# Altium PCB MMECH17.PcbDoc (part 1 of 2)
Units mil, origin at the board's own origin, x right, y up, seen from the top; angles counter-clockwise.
Board outline 2559.06 x 2205.16 mil, 4 copper layers (Top Layer, Ground Plane, Mid Layer 1, Bottom Layer), stack 56.756 mil thick; 96 components, 80 nets, 346 pads, 621 vias.
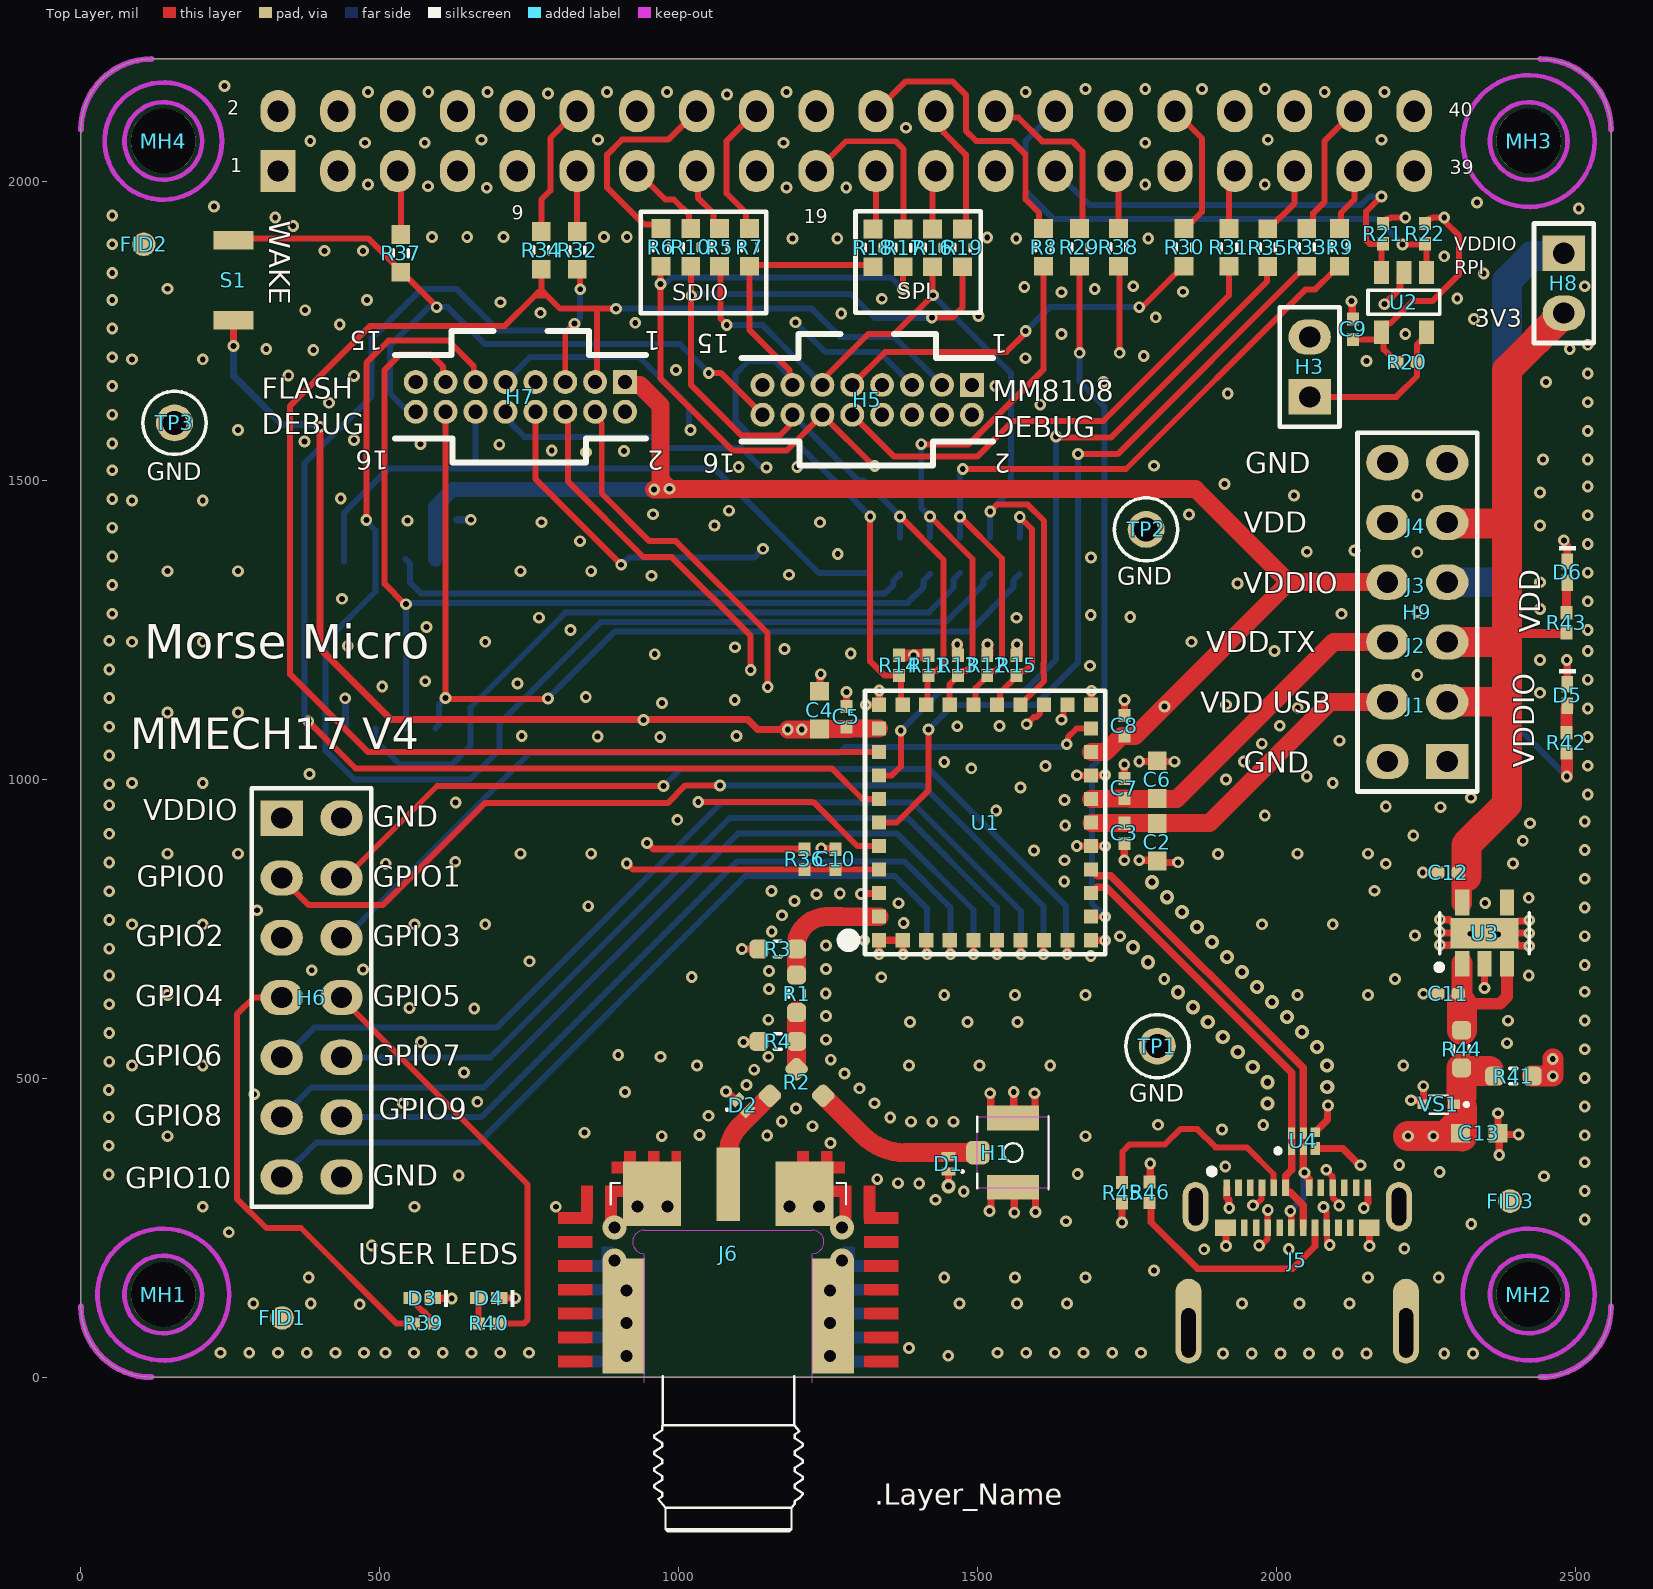
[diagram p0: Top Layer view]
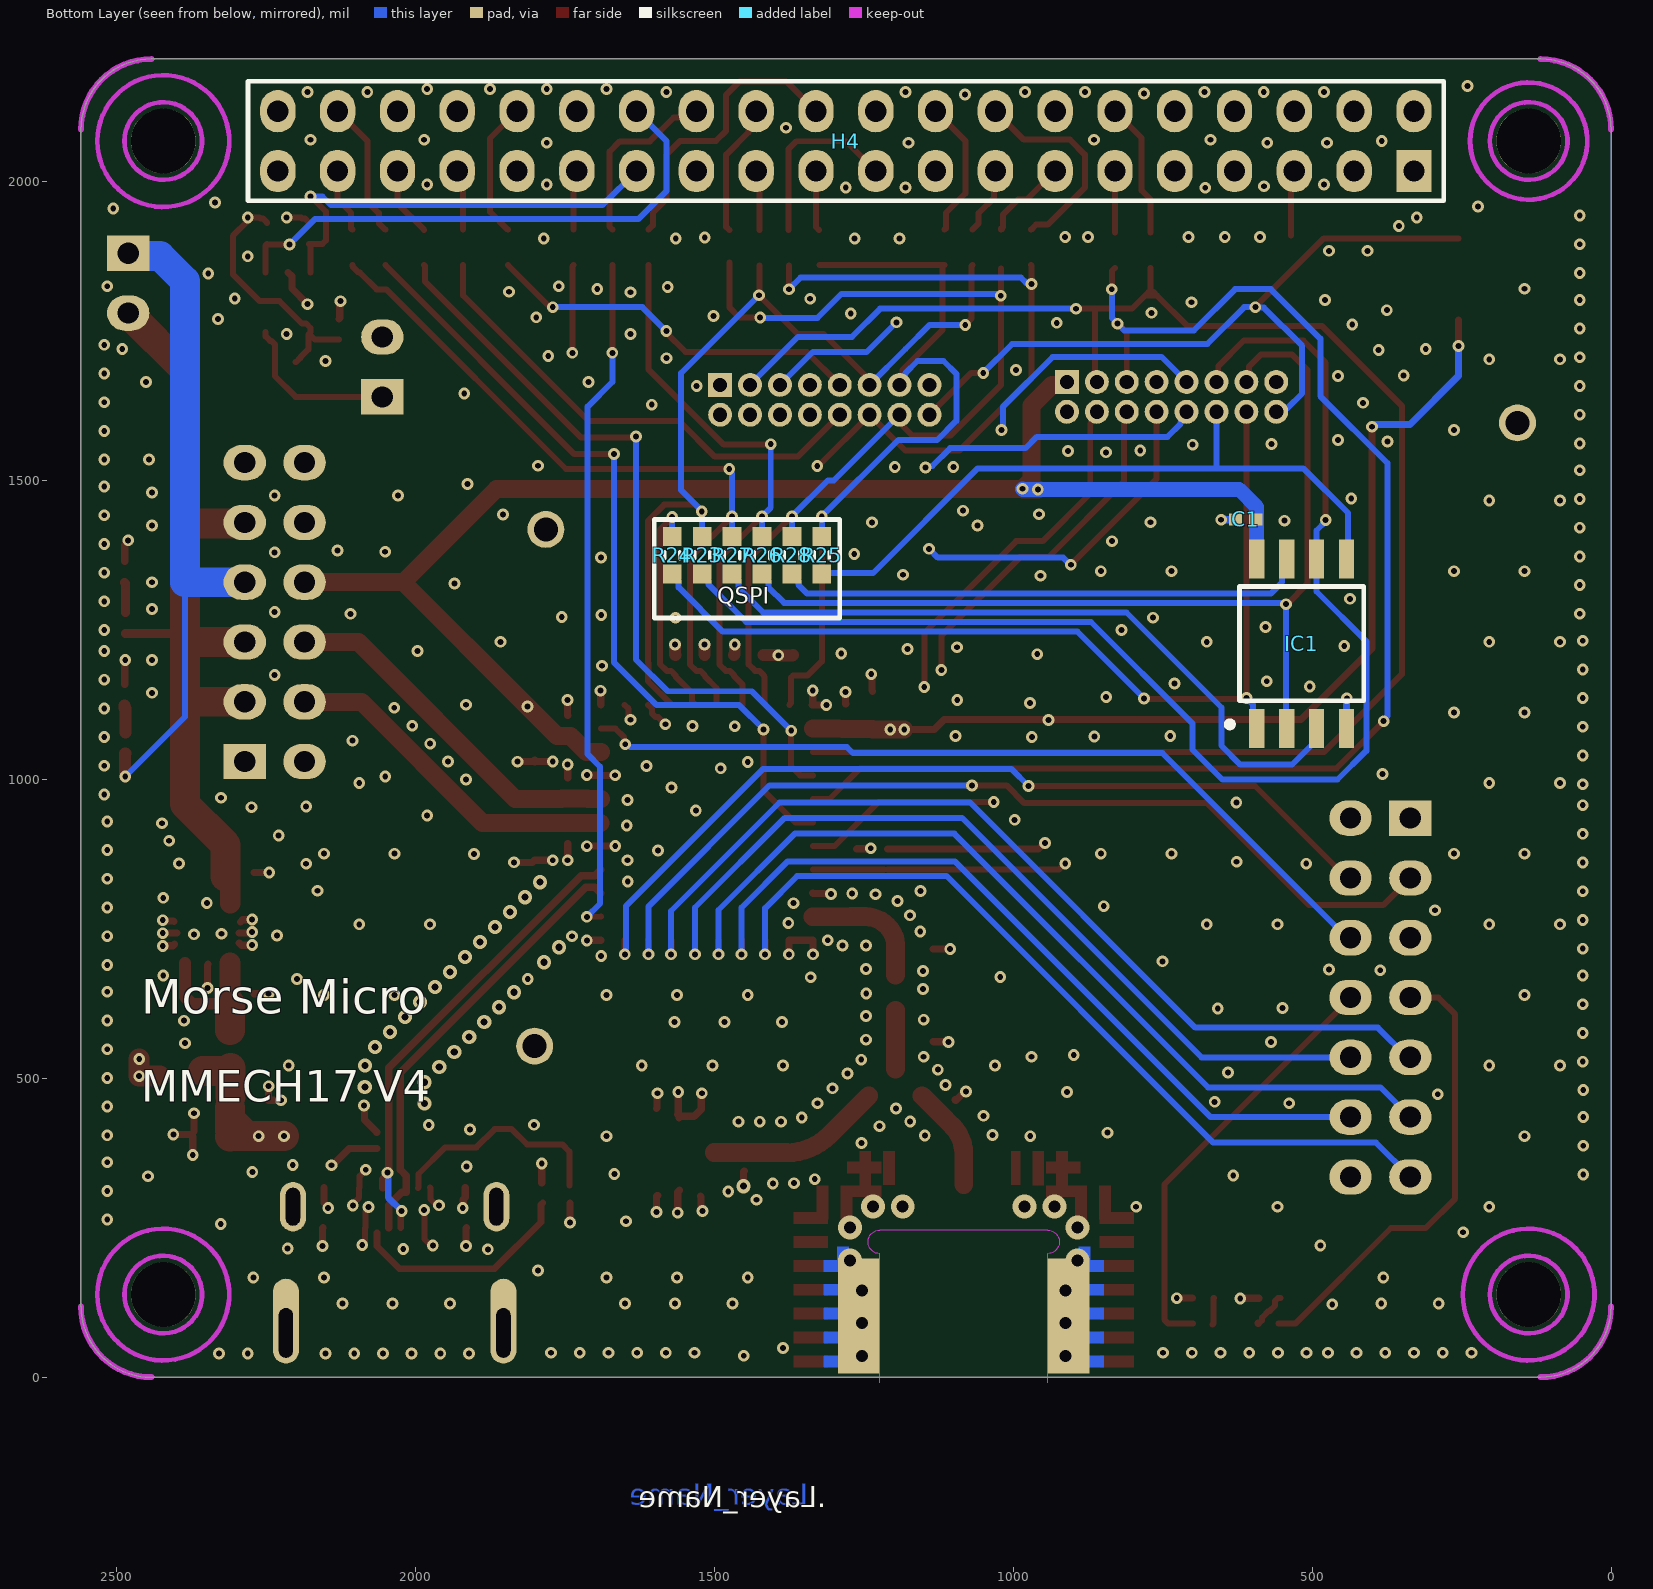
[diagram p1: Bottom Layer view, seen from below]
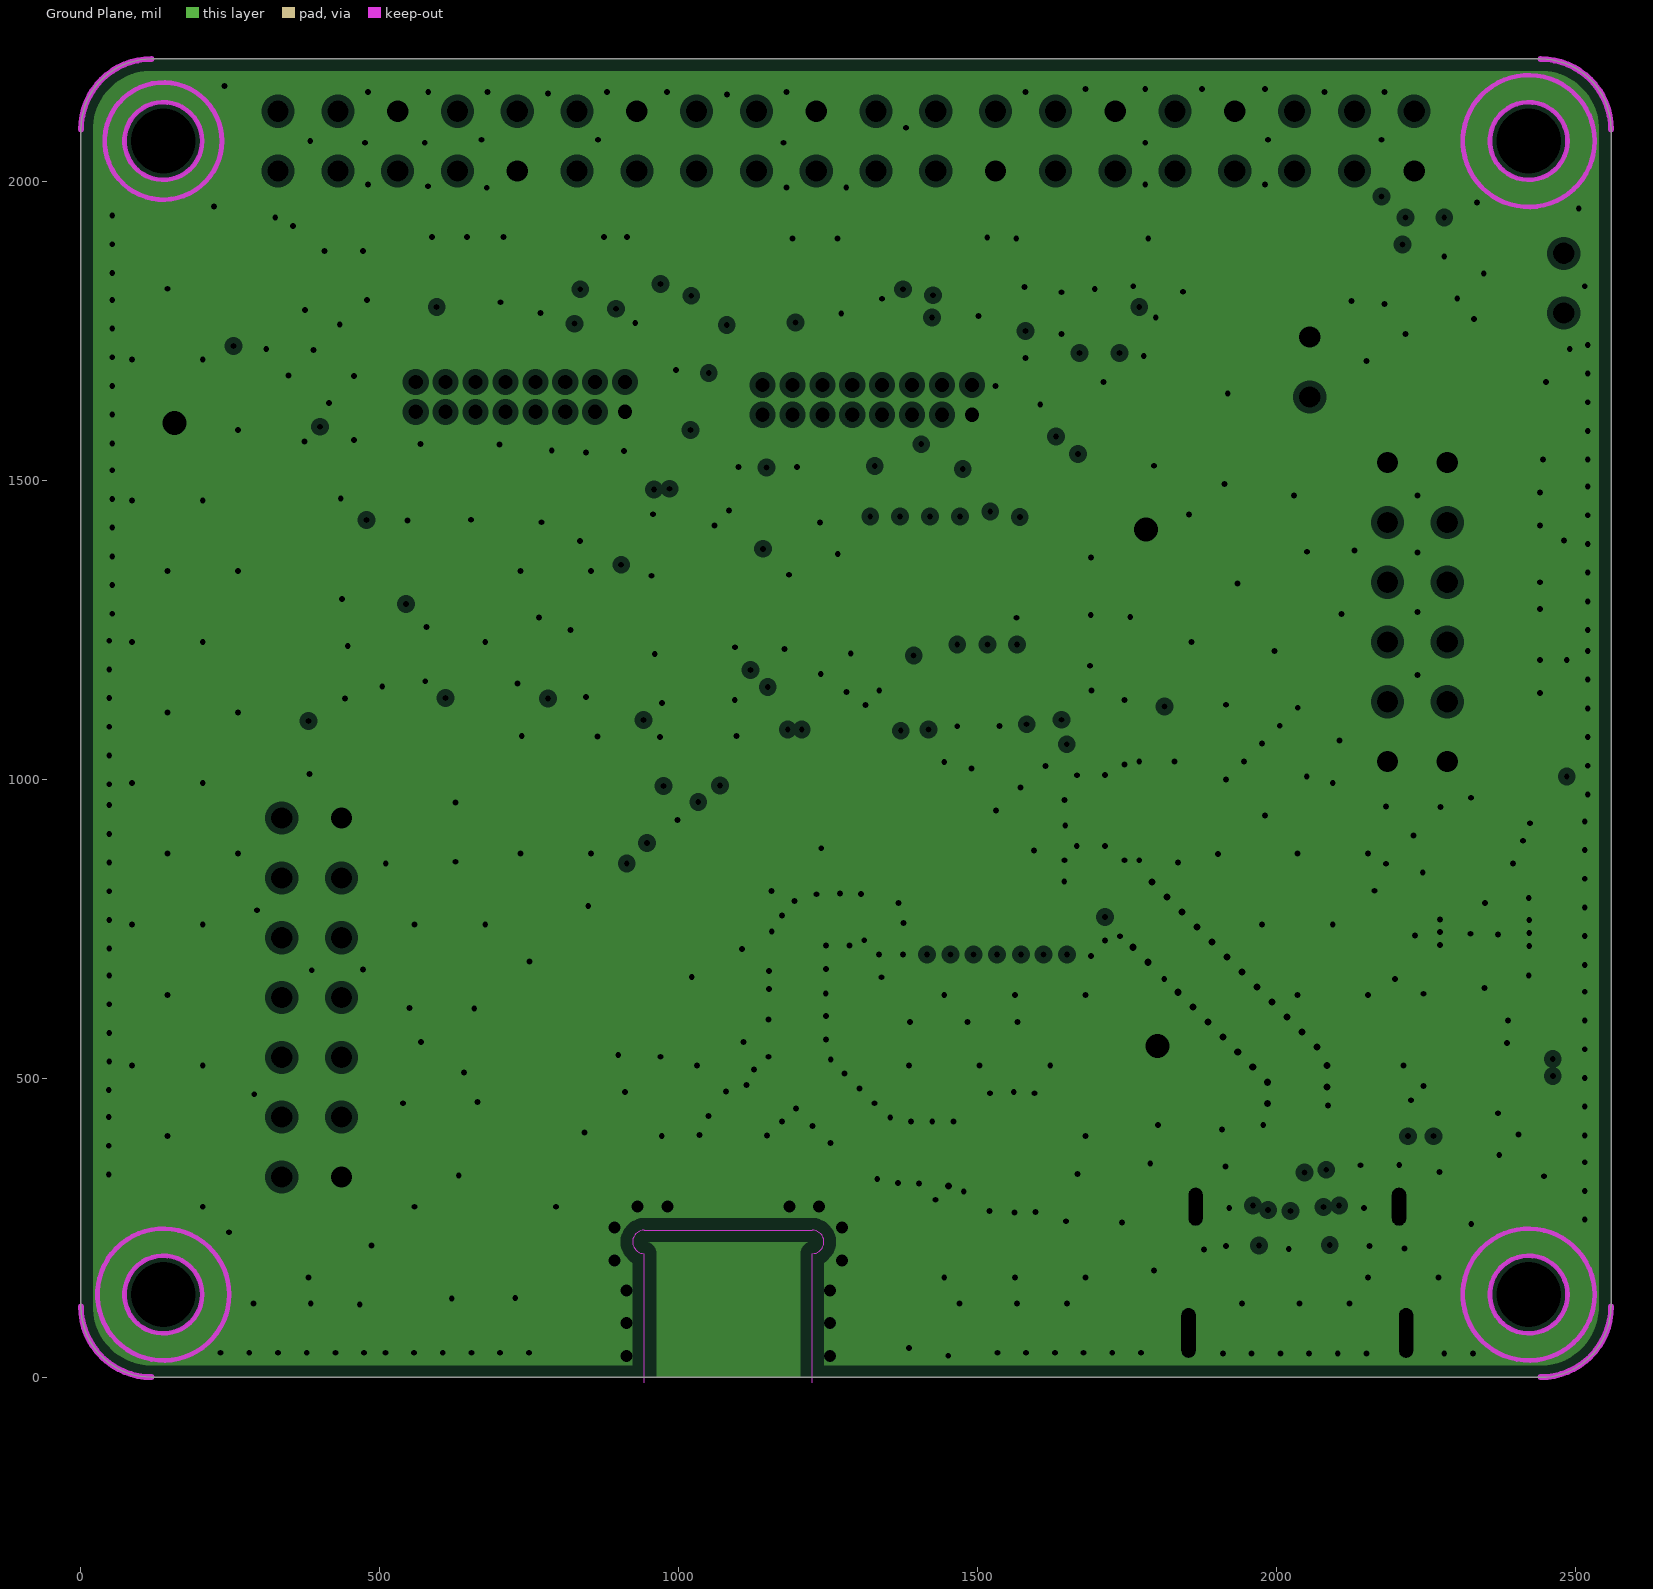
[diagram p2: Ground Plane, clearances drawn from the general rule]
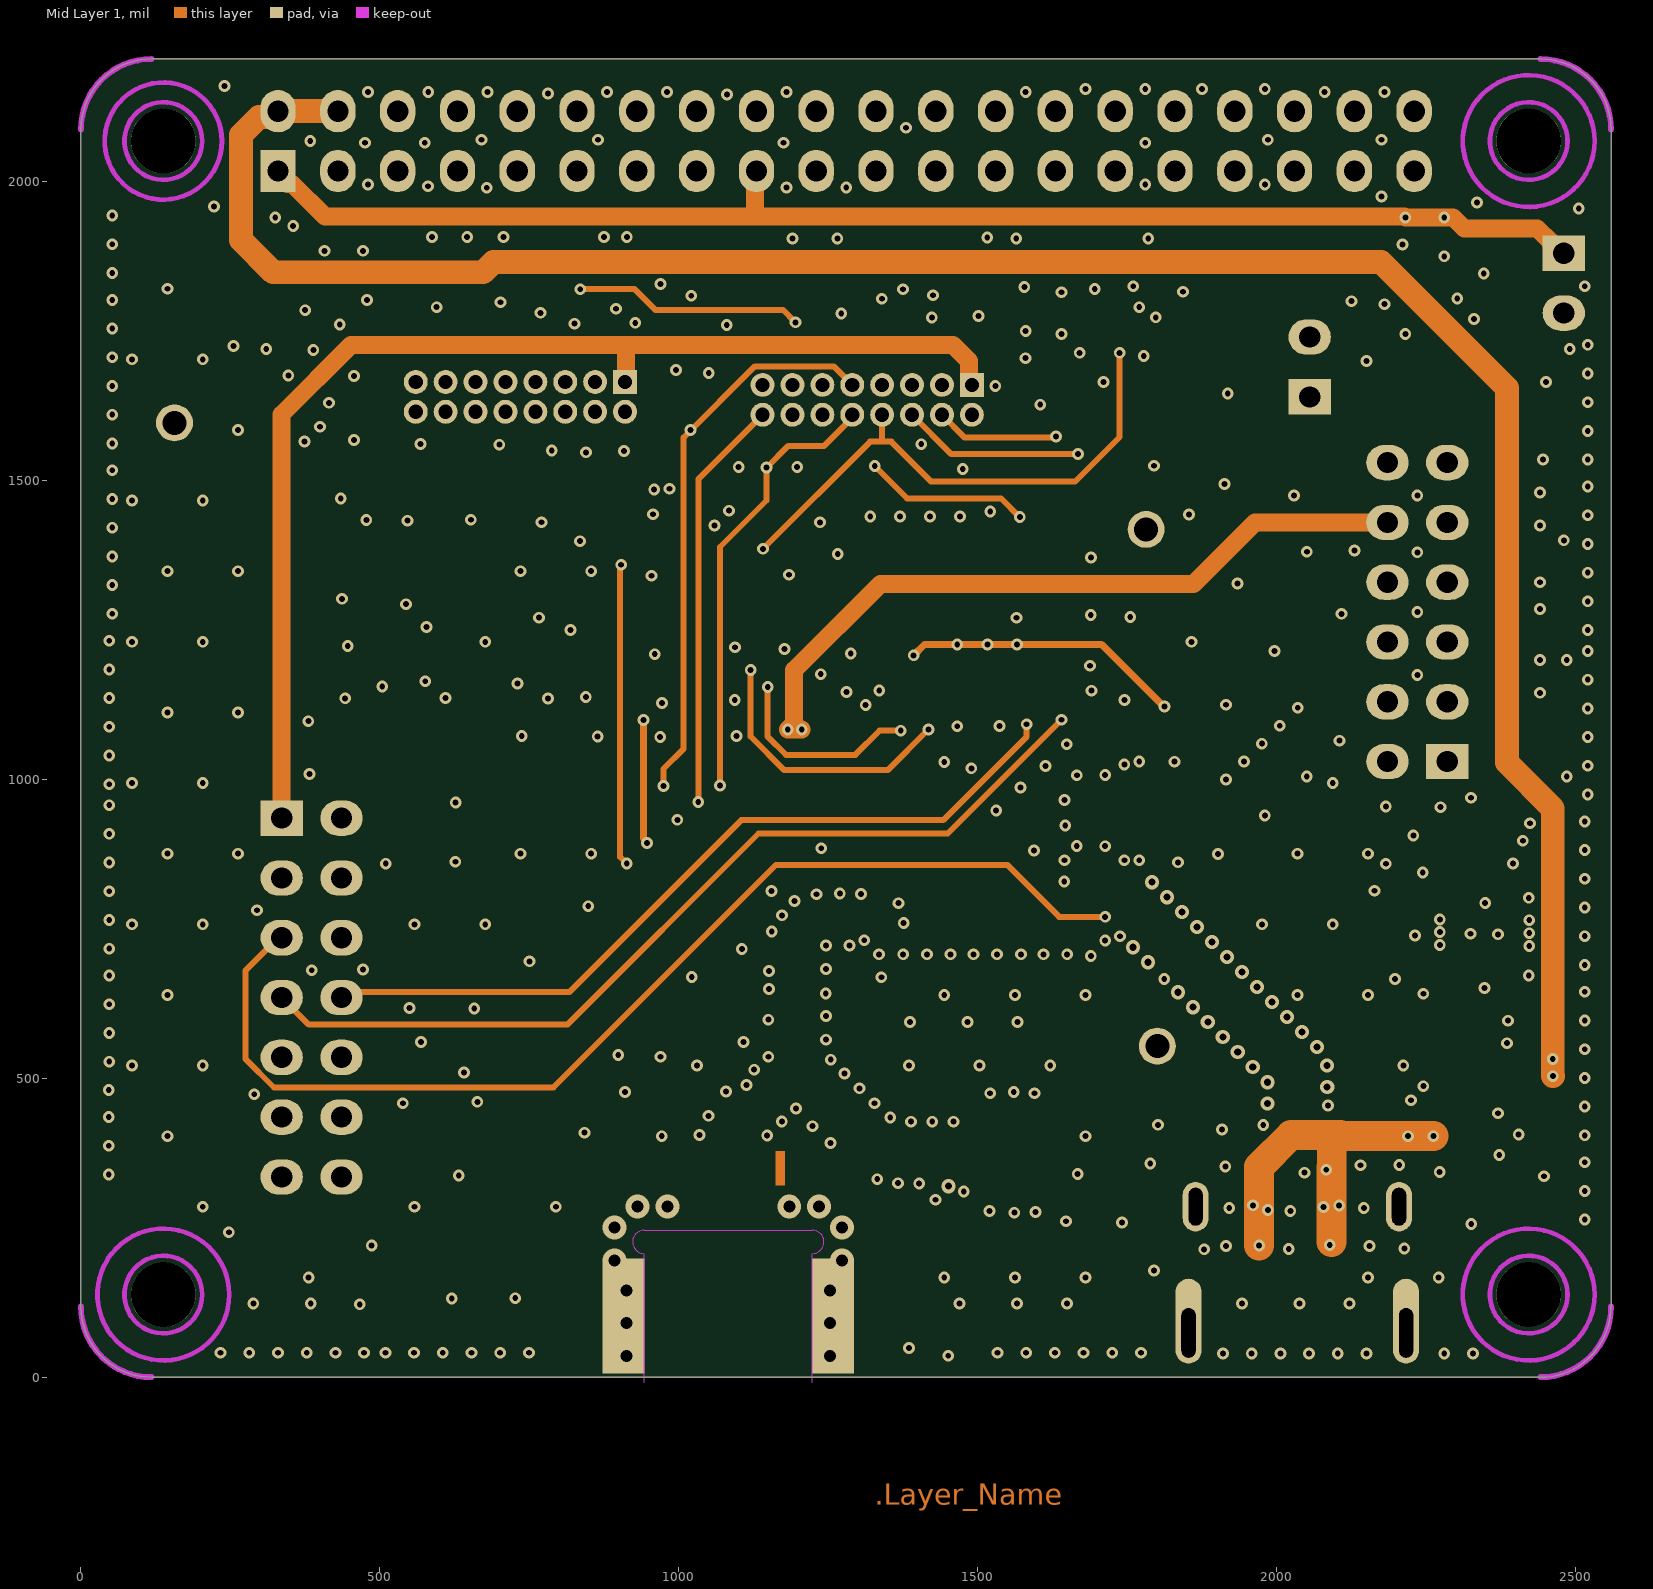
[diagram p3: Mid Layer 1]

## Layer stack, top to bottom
Top Solder: solder mask 0.787, PSR-4000-BN-Colour, Dk 4
Top Layer: signal copper 1.378
Dielectric 1: prepreg 12, PP, Dk 4.29
Ground Plane: plane copper 1.378, net GND
Dielectric 2: core 27.244, Core, Dk 4.29
Mid Layer 1: signal copper 1.378
Dielectric 3: prepreg 12, PP, Dk 4.29
Bottom Layer: signal copper 1.378
Bottom Solder: solder mask 0.787, PSR-4000-BN-Colour, Dk 4

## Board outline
0,118.54 0,2087.05 cw(c118.11,2087.05) 118.11,2205.16 2440.95,2205.16 cw(c2440.95,2087.05) 2559.06,2087.05 2559.06,118.54 2558.58,118.11 cw(c2440.47,118.11) 2440.47,0 118.54,0 118.11,0.43 cw(c118.11,118.54)

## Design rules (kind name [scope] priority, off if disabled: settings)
AcuteAngle [All] p0: scope1count=1 scope1_0_kind=Board scope1_0_value=Board scope2count=1 scope2_0_kind=Board scope2_0_value=Board commentlength=0 minimum=4.50000000000000E+0001
AcuteAngle [All] p1: minimum=4.50000000000000E+0001 checktracksonly=FALSE
AssemblyTestPointUsage [All] p0 off: scope1count=1 scope1_0_kind=Board scope1_0_value=Board scope2count=1 scope2_0_kind=Board scope2_0_value=Board commentlength=0
AssemblyTestPointUsage [All] p1 off:
AssemblyTestpoint [All] p0 off: scope1count=1 scope1_0_kind=Board scope1_0_value=Board scope2count=1 scope2_0_kind=Board scope2_0_value=Board commentlength=0
AssemblyTestpoint [All] p1 off: testpointundercomponent=TRUE minsize=40 maxsize=100 preferedsize=60 minholesize=0 maxholesize=40 preferedholesize=32 testpointgrid=1 usegrid=TRUE gridtolerance=0.01 allowsidetop=TRUE allowsidebottom=TRUE
BoardOutlineClearance [All] p0 off: scope1count=1 scope1_0_kind=Board scope1_0_value=Board scope2count=1 scope2_0_kind=Board scope2_0_value=Board commentlength=133 gap=5.98 // Protel DXP Scope 1 Expression Was: (not OnTopSilkscreen) AND (NOT OnBottomSilkscreen) and (not OnMultiLayer)    and  (not IsText)
BoardOutlineClearance BoardOutlineClearance_H2 [All] p0: scope1count=1 scope1_0_kind=Component scope1_0_value=H2 scope2count=1 scope2_0_kind=Board scope2_0_value=Board commentlength=0 gap=0
BoardOutlineClearance BoardOutlineClearance_H2 [InComponent('H2')] p1: gap=0 ignorepadtopadclearanceinfootprint=FALSE
BoardOutlineClearance [(not OnTopSilkscreen) AND (NOT OnBottomSilkscreen) and (not OnMultiLayer)    and  (not IsText)] p2: gap=5.98 ignorepadtopadclearanceinfootprint=FALSE
Clearance Clearance_SMA [All] p0 off: scope1count=1 scope1_0_kind=Footprint scope1_0_value=SM2924 scope2count=1 scope2_0_kind=Board scope2_0_value=Board commentlength=112 gap=0 // Protel DXP Scope 2 Expression Was: (OnLayer('Multi-Layer') OR OnLayer('Board') OR OnLayer('Keep-Out Layer'))
Clearance [All] p0: scope1count=1 scope1_0_kind=Board scope1_0_value=Board scope2count=1 scope2_0_kind=Board scope2_0_value=Board commentlength=0 gap=6
Clearance Clearance_RF [All] p0: scope1count=1 scope1_0_kind=NetClass scope1_0_value=RF-Net scope2count=1 scope2_0_kind=Board scope2_0_value=Board commentlength=0 gap=7.32
Clearance Clearance_RF_Poly [All] p0 off: scope1count=1 scope1_0_kind=Board scope1_0_value=Board scope2count=1 scope2_0_kind=NetClass scope2_0_value=RF-Net commentlength=50 gap=7.32 // Protel DXP Scope 1 Expression Was: (InPolygon)
Clearance Clearance_USB [All] p0 off: scope1count=1 scope1_0_kind=Board scope1_0_value=Board scope2count=1 scope2_0_kind=Board scope2_0_value=Board commentlength=66 gap=5.28 // Protel DXP Scope 1 Expression Was: InDifferentialPair('USB_D')
Clearance Clearance_SMA [HasFootprint('SM2924') vs (OnLayer('Multi-Layer') OR OnLayer('Board') OR OnLayer('Keep-Out Layer'))] p1: gap=0 ignorepadtopadclearanceinfootprint=TRUE
Clearance Clearance_USB [InDifferentialPair('USB_D')] p2: gap=5.28 ignorepadtopadclearanceinfootprint=TRUE except(6.2: Arc-Poly Track-Poly SMDPad-Poly)
Clearance Clearance_RF_Poly [(InPolygon) vs InNetClass('RF-Net')] p3: gap=7.32 ignorepadtopadclearanceinfootprint=TRUE
Clearance Clearance_RF [InNetClass('RF-Net')] p4: gap=7.32 ignorepadtopadclearanceinfootprint=TRUE
Clearance [All] p5: gap=6 ignorepadtopadclearanceinfootprint=TRUE
ComponentClearance ComponentClearance_Jumper [All] p0: scope1count=1 scope1_0_kind=Board scope1_0_value=Board scope2count=1 scope2_0_kind=Footprint scope2_0_value=FP-QPC02SXGN-RC-MFG commentlength=0 gap=0 collisioncheckmode=3
ComponentClearance [All] p0: scope1count=1 scope1_0_kind=Board scope1_0_value=Board scope2count=1 scope2_0_kind=Board scope2_0_value=Board commentlength=0 gap=10 collisioncheckmode=3
ComponentClearance ComponentClearance_Jumper [All vs HasFootprint('FP-QPC02SXGN-RC-MFG')] p1: gap=0 collisioncheckmode=3 verticalgap=-1 showdistances=FALSE
ComponentClearance [All] p2: gap=10 collisioncheckmode=3 verticalgap=10 showdistances=FALSE
DiffPairsRouting [All] p0 off: scope1count=1 scope1_0_kind=Board scope1_0_value=Board scope2count=1 scope2_0_kind=Board scope2_0_value=Board commentlength=66 // Protel DXP Scope 1 Expression Was: InDifferentialPair('USB_D')
DiffPairsRouting [InDifferentialPair('USB_D')] p1: maxlimit=7.1 minlimit=5.29 mostfreqgap=5.29 toplayer_mingap=6.5 toplayer_maxgap=6.5 toplayer_prefgap=6.5 toplayer_minwidth=12.5 toplayer_maxwidth=12.5 toplayer_prefwidth=12.5 bottomlayer_maxgap=5.29 bottomlayer_minwidth=11.02 bottomlayer_maxwidth=11.02 bottomlayer_prefwidth=11.02 impedanceprofiledriven=TRUE impedanceprofileid={D3D6B15B-8A59-4732-A24C-BA8DB3C77CBB} impedanceprofilevalue=90.000000 maxuncoupledlength=500
FabricationTestPointUsage [All] p0 off: scope1count=1 scope1_0_kind=Board scope1_0_value=Board scope2count=1 scope2_0_kind=Board scope2_0_value=Board commentlength=0 valid=0 allowmultiple=FALSE
FabricationTestPointUsage [All] p1 off: valid=0 allowmultiple=FALSE
FabricationTestpoint [All] p0 off: scope1count=1 scope1_0_kind=Board scope1_0_value=Board scope2count=1 scope2_0_kind=Board scope2_0_value=Board commentlength=0 side=3 testpointundercomponent=TRUE minsize=40 maxsize=100 preferedsize=60 minholesize=0 maxholesize=40 preferedholesize=32 testpointgrid=1
FabricationTestpoint [All] p1 off: side=3 testpointundercomponent=TRUE minsize=40 maxsize=100 preferedsize=60 minholesize=0 maxholesize=40 preferedholesize=32 testpointgrid=1 allowsidetop=TRUE allowsidebottom=TRUE usegrid=TRUE gridtolerance=0.01
FanoutControl Fanout_Default [All] p0 off: scope1count=1 scope1_0_kind=Board scope1_0_value=Board scope2count=1 scope2_0_kind=Board scope2_0_value=Board commentlength=30 // Fanout_Default (Default Rule)
FanoutControl Fanout_Small [All] p0 off: scope1count=1 scope1_0_kind=Board scope1_0_value=Board scope2count=1 scope2_0_kind=Board scope2_0_value=Board commentlength=84 // Protel DXP Scope 1 Expression Was: (CompPinCount < 5)   Fanout_Small (Default Rule)
FanoutControl Fanout_SOIC [All] p0 off: scope1count=1 scope1_0_kind=Board scope1_0_value=Board scope2count=1 scope2_0_kind=Board scope2_0_value=Board commentlength=71 // Protel DXP Scope 1 Expression Was: IsSOIC   Fanout_SOIC (Default Rule)
FanoutControl Fanout_LCC [All] p0 off: scope1count=1 scope1_0_kind=Board scope1_0_value=Board scope2count=1 scope2_0_kind=Board scope2_0_value=Board commentlength=69 // Protel DXP Scope 1 Expression Was: IsLCC   Fanout_LCC (Default Rule)
FanoutControl Fanout_BGA [All] p0 off: scope1count=1 scope1_0_kind=Board scope1_0_value=Board scope2count=1 scope2_0_kind=Board scope2_0_value=Board commentlength=69 // Protel DXP Scope 1 Expression Was: IsBGA   Fanout_BGA (Default Rule)
FanoutControl Fanout_BGA [IsBGA] p1 off: bgadir=Out bgaviamode=Centered fanoutstyle=Auto fanoutdirection=Alternating viagrid=1 // Fanout_BGA (Default Rule)
FanoutControl Fanout_LCC [IsLCC] p2 off: bgadir=Out bgaviamode=Centered fanoutstyle=Auto fanoutdirection=Alternating viagrid=1 // Fanout_LCC (Default Rule)
FanoutControl Fanout_SOIC [IsSOIC] p3 off: bgadir=Out bgaviamode=Centered fanoutstyle=Auto fanoutdirection=Alternating viagrid=1 // Fanout_SOIC (Default Rule)
FanoutControl Fanout_Small [(CompPinCount < 5)] p4 off: bgadir=Out bgaviamode=Centered fanoutstyle=Auto fanoutdirection=OutThenIn viagrid=1 // Fanout_Small (Default Rule)
FanoutControl Fanout_Default [All] p5 off: bgadir=Out bgaviamode=Centered fanoutstyle=Auto fanoutdirection=Alternating viagrid=1 // Fanout_Default (Default Rule)
Height [All] p0 off: scope1count=1 scope1_0_kind=Board scope1_0_value=Board scope2count=1 scope2_0_kind=Board scope2_0_value=Board commentlength=0
Height TP1 [All] p0: scope1count=1 scope1_0_kind=Component scope1_0_value=TP1 scope2count=1 scope2_0_kind=Board scope2_0_value=Board commentlength=0
Height TP1 [InComponent('TP1')] p1: minheight=0 maxheight=472.44 prefheight=118.11
Height [All] p2 off: minheight=0 maxheight=1000 prefheight=500
HoleSize [All] p0: scope1count=1 scope1_0_kind=Board scope1_0_value=Board scope2count=1 scope2_0_kind=Board scope2_0_value=Board commentlength=0 absolutevalues=TRUE maxlimit=200 minlimit=7.87 maxpercent=80.000 minpercent=20.000
HoleSize [All] p1: absolutevalues=TRUE maxlimit=200 minlimit=7.87 maxpercent=80.000 minpercent=20.000
HoleToHoleClearance [All] p0: scope1count=1 scope1_0_kind=Board scope1_0_value=Board scope2count=1 scope2_0_kind=Board scope2_0_value=Board commentlength=0
HoleToHoleClearance [All] p1: gap=8 allowstackedmicrovias=TRUE
LayerPairs [All] p0 off: scope1count=1 scope1_0_kind=Board scope1_0_value=Board scope2count=1 scope2_0_kind=Board scope2_0_value=Board commentlength=0 enforce=TRUE
LayerPairs [All] p1 off: enforce=TRUE
MatchedLengths MatchLengths_U1_Passives_J5 [All] p0: scope1count=1 scope1_0_kind=NetClass scope1_0_value=SDIO scope2count=1 scope2_0_kind=Board scope2_0_value=Board commentlength=0 tolerance=100 amplitude=200 gap=20 style=90-Degree
MatchedLengths MatchLengths_U1_Passives_J5 [InNetClass('SDIO')] p1: tolerance=100 checknetsindiffpair=FALSE checkdiffpairvsdiffpair=TRUE checkxsignals=TRUE checkothers=TRUE
MinimumSolderMaskSliver [All] p0 off: scope1count=1 scope1_0_kind=Board scope1_0_value=Board scope2count=1 scope2_0_kind=Board scope2_0_value=Board commentlength=108 // Protel DXP Scope 1 Expression Was: not InComponent('U4','U1','U5','U6','U7','U8','U9','U10', 'H7', 'H5')
MinimumSolderMaskSliver [not InComponent('U4','U1','U5','U6','U7','U8','U9','U10', 'H7', 'H5')] p1: minsoldermaskwidth=2.36
NetAntennae [All] p0: scope1count=1 scope1_0_kind=Board scope1_0_value=Board scope2count=1 scope2_0_kind=Board scope2_0_value=Board commentlength=0
PasteMaskExpansion [All] p0: scope1count=1 scope1_0_kind=Board scope1_0_value=Board scope2count=1 scope2_0_kind=Board scope2_0_value=Board commentlength=0 expansion=0
PlaneClearance [All] p0: scope1count=1 scope1_0_kind=Board scope1_0_value=Board scope2count=1 scope2_0_kind=Board scope2_0_value=Board commentlength=0 clearance=10
PlaneClearance [All] p1: clearance=10
PlaneConnect PlaneConnect_SMA [All] p0 off: scope1count=1 scope1_0_kind=Board scope1_0_value=Board scope2count=1 scope2_0_kind=Board scope2_0_value=Board commentlength=63 planeconnectstyle=Direct reliefexpansion=20 reliefentries=4 reliefconductorwidth=10 reliefairgap=10 // Protel DXP Scope 1 Expression Was: (HasFootprint('SM2924'))
PlaneConnect [All] p0: scope1count=1 scope1_0_kind=Board scope1_0_value=Board scope2count=1 scope2_0_kind=Board scope2_0_value=Board commentlength=0 planeconnectstyle=Relief reliefexpansion=20 reliefentries=4 reliefconductorwidth=10 reliefairgap=10
PlaneConnect PlaneConnect_SMA [(HasFootprint('SM2924'))] p1: planeconnectstyle=Direct reliefexpansion=20 reliefentries=4 reliefconductorwidth=10 reliefairgap=10
PlaneConnect [All] p2: pad.planeconnectstyle=Relief pad.reliefexpansion=20 pad.reliefentries=4 pad.reliefconductorwidth=10 pad.reliefairgap=10 via.planeconnectstyle=Direct via.reliefexpansion=20 via.reliefentries=4 via.reliefconductorwidth=10 via.reliefairgap=10
PolygonConnect PolygonConnect_SMA [All] p0 off: scope1count=1 scope1_0_kind=Board scope1_0_value=Board scope2count=1 scope2_0_kind=Board scope2_0_value=Board commentlength=63 connectstyle=Direct reliefconductorwidth=10 reliefentries=4 polygonreliefangle="90 Angle" // Protel DXP Scope 1 Expression Was: (HasFootprint('SM2924'))
PolygonConnect [All] p0: scope1count=1 scope1_0_kind=Board scope1_0_value=Board scope2count=1 scope2_0_kind=Board scope2_0_value=Board commentlength=0 connectstyle=Relief reliefconductorwidth=10 reliefentries=4 polygonreliefangle="90 Angle"
PolygonConnect PolygonConnect_SMA [(HasFootprint('SM2924'))] p1: connectstyle=Direct reliefconductorwidth=10 reliefentries=4 polygonreliefangle="90 Angle" airgapwidth=10
PolygonConnect [All] p2: thpad.connectstyle=Relief thpad.reliefconductorwidth=10 thpad.reliefentries=4 thpad.polygonreliefangle="90 Angle" thpad.airgapwidth=10 smdpad.connectstyle=Direct smdpad.reliefconductorwidth=10 smdpad.reliefentries=4 smdpad.polygonreliefangle="90 Angle" smdpad.airgapwidth=10 via.connectstyle=Direct via.reliefconductorwidth=10 via.reliefentries=4 via.polygonreliefangle="90 Angle" via.airgapwidth=10
RoutingCorners [All] p0: scope1count=1 scope1_0_kind=Board scope1_0_value=Board scope2count=1 scope2_0_kind=Board scope2_0_value=Board commentlength=0 cornerstyle=45-Degree minsetback=100 maxsetback=100
RoutingLayers [All] p0: scope1count=1 scope1_0_kind=Board scope1_0_value=Board scope2count=1 scope2_0_kind=Board scope2_0_value=Board commentlength=0 top layer=Automatic mid layer 3=Automatic bottom layer=Automatic
RoutingPriority [All] p0: scope1count=1 scope1_0_kind=Board scope1_0_value=Board scope2count=1 scope2_0_kind=Board scope2_0_value=Board commentlength=0
RoutingTopology [All] p0: scope1count=1 scope1_0_kind=Board scope1_0_value=Board scope2count=1 scope2_0_kind=Board scope2_0_value=Board commentlength=0 topology=Shortest
RoutingVias [All] p0: scope1count=1 scope1_0_kind=Board scope1_0_value=Board scope2count=1 scope2_0_kind=Board scope2_0_value=Board commentlength=0 holewidth=11.81 width=23.62 viastyle="Through Hole" minholewidth=7.87 minwidth=15.75 maxholewidth=28 maxwidth=50
RoutingVias [All] p1: holewidth=11.81 width=23.62 viastyle="Through Hole" minholewidth=7.87 minwidth=15.75 maxholewidth=28 maxwidth=50
ShortCircuit ShortCircuit_SMA [All] p0 off: scope1count=1 scope1_0_kind=Board scope1_0_value=Board scope2count=1 scope2_0_kind=Layer scope2_0_value=TOP commentlength=80 allowed=TRUE // Protel DXP Scope 1 Expression Was: (InNet('GND') AND HasFootprint('SM2924'))
ShortCircuit [All] p0: scope1count=1 scope1_0_kind=Board scope1_0_value=Board scope2count=1 scope2_0_kind=Board scope2_0_value=Board commentlength=0 allowed=FALSE
ShortCircuit ShortCircuit_SMA [(InNet('GND') AND HasFootprint('SM2924')) vs OnLayer('Multi-Layer')] p1: allowed=TRUE
ShortCircuit [All] p2: allowed=FALSE
SilkToBoardRegionClearance [All] p0: scope1count=1 scope1_0_kind=Board scope1_0_value=Board scope2count=1 scope2_0_kind=Board scope2_0_value=Board commentlength=0
SilkToSilkClearance [All] p0 off: scope1count=1 scope1_0_kind=Board scope1_0_value=Board scope2count=1 scope2_0_kind=Board scope2_0_value=Board commentlength=0
SilkToSilkClearance [All] p1 off: silktosilkclearance=8
SilkToSolderMaskClearance [All] p0 off: scope1count=1 scope1_0_kind=Board scope1_0_value=Board scope2count=1 scope2_0_kind=Board scope2_0_value=Board commentlength=44 // Protel DXP Scope 1 Expression Was: IsPad
SilkToSolderMaskClearance [IsPad] p1 off: minsilkscreentomaskgap=4 clearancetoexposedcopper=TRUE
SolderMaskExpansion [All] p0: scope1count=1 scope1_0_kind=Board scope1_0_value=Board scope2count=1 scope2_0_kind=Board scope2_0_value=Board commentlength=0 expansion=4
SolderMaskExpansion [All] p1: expansion=4 istentingtop=FALSE
SupplyNets "Schematic Supply Nets_11" [All] p0: scope1count=1 scope1_0_kind=Net scope1_0_value=VDD_TX scope2count=1 scope2_0_kind=Board scope2_0_value=Board commentlength=0 voltage=0.000
SupplyNets "Schematic Supply Nets_10" [All] p0: scope1count=1 scope1_0_kind=Net scope1_0_value=VDD scope2count=1 scope2_0_kind=Board scope2_0_value=Board commentlength=0 voltage=0.000
SupplyNets "Schematic Supply Nets_8" [All] p0: scope1count=1 scope1_0_kind=Net scope1_0_value=VDD_3V3 scope2count=1 scope2_0_kind=Board scope2_0_value=Board commentlength=0 voltage=0.000
SupplyNets "Schematic Supply Nets_6" [All] p0: scope1count=1 scope1_0_kind=Net scope1_0_value=VDDIO_RPI scope2count=1 scope2_0_kind=Board scope2_0_value=Board commentlength=0 voltage=0.000
SupplyNets "Schematic Supply Nets_5" [All] p0: scope1count=1 scope1_0_kind=Net scope1_0_value=VDD5 scope2count=1 scope2_0_kind=Board scope2_0_value=Board commentlength=0 voltage=0.000
SupplyNets "Schematic Supply Nets_4" [All] p0: scope1count=1 scope1_0_kind=Net scope1_0_value=5V_USB scope2count=1 scope2_0_kind=Board scope2_0_value=Board commentlength=0 voltage=0.000
SupplyNets "Schematic Supply Nets_3" [All] p0: scope1count=1 scope1_0_kind=Net scope1_0_value=GND scope2count=1 scope2_0_kind=Board scope2_0_value=Board commentlength=0 voltage=0.000
SupplyNets "Schematic Supply Nets_2" [All] p0: scope1count=1 scope1_0_kind=Net scope1_0_value=VDD_USB scope2count=1 scope2_0_kind=Board scope2_0_value=Board commentlength=0 voltage=0.000
SupplyNets "Schematic Supply Nets_1" [All] p0: scope1count=1 scope1_0_kind=Net scope1_0_value=VDD5_RPI scope2count=1 scope2_0_kind=Board scope2_0_value=Board commentlength=0 voltage=0.000
SupplyNets "Schematic Supply Nets" [All] p0: scope1count=1 scope1_0_kind=Net scope1_0_value=VDDIO scope2count=1 scope2_0_kind=Board scope2_0_value=Board commentlength=0 voltage=0.000
SupplyNets "Schematic Supply Nets_11" [InNet('VDD_TX')] p1: voltage=0.000
SupplyNets "Schematic Supply Nets_10" [InNet('VDD')] p2: voltage=0.000
SupplyNets "Schematic Supply Nets_8" [InNet('VDD_3V3')] p3: voltage=0.000
SupplyNets "Schematic Supply Nets_6" [InNet('VDDIO_RPI')] p4: voltage=0.000
SupplyNets "Schematic Supply Nets_5" [InNet('VDD5')] p5: voltage=0.000
SupplyNets "Schematic Supply Nets_4" [InNet('5V_USB')] p6: voltage=0.000
SupplyNets "Schematic Supply Nets_3" [InNet('GND')] p7: voltage=0.000
SupplyNets "Schematic Supply Nets_2" [InNet('VDD_USB')] p8: voltage=0.000
SupplyNets "Schematic Supply Nets_1" [InNet('VDD5_RPI')] p9: voltage=0.000
SupplyNets "Schematic Supply Nets" [InNet('VDDIO')] p10: voltage=0.000
UnConnectedPin [All] p0 off: scope1count=1 scope1_0_kind=Board scope1_0_value=Board scope2count=1 scope2_0_kind=Board scope2_0_value=Board commentlength=0
UnConnectedPin [All] p1 off:
UnRoutedNet [All] p0: scope1count=1 scope1_0_kind=Board scope1_0_value=Board scope2count=1 scope2_0_kind=Board scope2_0_value=Board commentlength=0
UnRoutedNet [All] p1: checkbadconnections=TRUE
UnpouredPolygon [All] p0: scope1count=1 scope1_0_kind=Board scope1_0_value=Board scope2count=1 scope2_0_kind=Board scope2_0_value=Board commentlength=0
Width [All] p0: scope1count=1 scope1_0_kind=Board scope1_0_value=Board scope2count=1 scope2_0_kind=Board scope2_0_value=Board commentlength=0 maxlimit=50 minlimit=10 preferedwidth=10
Width "RF Width" [All] p0: scope1count=1 scope1_0_kind=NetClass scope1_0_value=RF-Net scope2count=1 scope2_0_kind=Board scope2_0_value=Board commentlength=0 maxlimit=35.43 minlimit=7 preferedwidth=10
Width "RF Width" [InNetClass('RF-Net')] p1: maxlimit=35.43 minlimit=7 preferedwidth=10 toplayer_minwidth=31.5 toplayer_maxwidth=31.5 toplayer_prefwidth=31.5 impedanceprofiledriven=TRUE impedanceprofileid={2BAD1660-FF1E-4629-AB45-93BC2CD73358} impedanceprofilevalue=50.000000 minimp=50.000000 maximp=50.000000 favimp=50.000000
Width [All] p2: maxlimit=50 minlimit=10 preferedwidth=10 minimp=50.000000 maximp=50.000000 favimp=50.000000
8 further rules are at their usual default settings.

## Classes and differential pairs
component class SOT-23: U3
net class RF-Net: NetD1_2 NetD2_2 NetR1_1 NetR1_2
component class PCB_PATTERN: FID1 FID2 FID3 MH1 MH2 MH3 MH4
component class COMP_OTHER: H1 H3 H4 H6 H8 H9 J5 S1 U1 U2 U4
component class CHIP_OTHER: C2 C4 C6 C13 D3 D4 D5 D6 R1 R3 R4 R37 R41 R44
component class CHIP_MICRO: C1 C3 C5 C7 C8 C9 C10 C11 C12 R2 R5 R6 R7 R8 R9 R10 R11 R12 R13 R14 R15 R16 R17 R18 R19 R20 R21 R22 R23 R24 R25 R26 R27 R28 R29 R30 R31 R32 R33 R34 R35 R36 R38 R39 R40 R42 R43 R45 R46 VS1
component class MMECH17_Power: C11 C12 C13 D5 D6 FID1 FID2 FID3 H8 H9 J1 J2 J3 J4 J5 MH1 MH2 MH3 MH4 R41 R42 R43 R44 R45 R46 TP1 TP2 TP3 U3 U4 VS1
component class MMECH17_Module: C1 C2 C3 C4 C5 C6 C7 C8 C9 C10 D1 D2 D3 D4 H1 H3 H4 H5 H6 H7 IC1 J6 R1 R2 R3 R4 R5 R6 R7 R8 R9 R10 R11 R12 R13 R14 R15 R16 R17 R18 R19 R20 R21 R22 R23 R24 R25 R26 R27 R28 R29 R30 R31 R32 R33 R34 R35 R36 R37 R38 R39 R40 S1 U1 U2
differential pair " ": +USB_D_P -USB_D_N

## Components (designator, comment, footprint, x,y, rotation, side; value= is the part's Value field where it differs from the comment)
C1 "C0402C104K8RACTU" 0402_cap 611.22,1435.04 r180 bottom
C2 "GRM188R61E106MA73J" 0603_cap 1800,895 r270 top
C3 "C0402C104K8RACTU" 0402_cap 1745,910 r270 top
C4 "GRM188R61E106MA73J" 0603_cap 1235.24,1116.14 r90 top
C5 "C0402C104K8RACTU" 0402_cap 1280.16,1105 r270 top
C6 "GRM188R61E106MA73J" 0603_cap 1800,1000 r90 top
C7 "C0402C104K8RACTU" 0402_cap 1745,985 r90 top
C8 "C0402C104K8RACTU" 0402_cap 1745,1090 r90 top
C9 "C0402C104K8RACTU" 0402_cap 2127.5,1753.08 r270 top
C10 "JMK105BJ225MV-F" 0402_cap 1261.72,866.34 r90 top
C11 "CL05A106MP8NUB8" 0402_cap_rnd 2286.42,641.73 r180 top
C12 "CL05A106MP8NUB8" 0402_cap_rnd 2286.42,844.49 r180 top
C13 "GRM188R61E106MA73J" 0603_cap 2338.58,408.46 r0 top
D1 "ESD103B102ELE6327XTMA1" INF-TSLP-2-20_V 1450.79,357.28 r180 top
D2 "ESD103B102ELE6327XTMA1" INF-TSLP-2-20_V 1106.49,455.52 r45 top
D3 "XZVGR68W-3" LED_0402_GREEN 570.87,132.87 r0 top
D4 "XZMDK68W-2" LED_0402_RED 682.09,132.87 r0 top
D5 "XZVGR68W-3" LED_0402_GREEN 2485.8,1141.26 r90 top
D6 "XZVGR68W-3" LED_0402_GREEN 2485.8,1346.93 r90 top
FID1 "1mm Round Fiducial, 0.5mm Space" FIDUCIAL_1MM 336.36,99.56 r90 top
FID2 "1mm Round Fiducial, 0.5mm Space" FIDUCIAL_1MM 105,1895 r0 top
FID3 "1mm Round Fiducial, 0.5mm Space" FIDUCIAL_1MM 2390,295 r90 top
H1 "U.FL-R-SMT" U_FL-R-SMT 1559.06,375.98 r270 top
H3 "DNF" HDR1X2_DNF 2055,1690 r90 top
H4 "PPPC202LFBN-RC" HDR2X20F 1279.72,2067.72 r0 bottom
H5 "FTSH-108-01-F-D-K" FTSH_108_D_K 1315,1635 r180 top
H6 "PBC07DFAN" HDR2X7 385.8,635.41 r270 top
H7 "FTSH-108-01-F-D-K" FTSH_108_D_K 735,1640 r180 top
H8 "2011-1X02G00SB-1" HDR1X2 2480,1830 r270 top
H9 "90131-0126" HDR2X6 2235,1280 r90 top
IC1 "W25Q64JVSSIQ" SOIC127P790X216-8N 517.65,1227.35 r90 bottom
J1 "QPC02SXGN-RC" FP-QPC02SXGN-RC-MFG 2232.28,1124.02 r0 top
J2 "QPC02SXGN-RC" FP-QPC02SXGN-RC-MFG 2232.28,1223.43 r0 top
J3 "QPC02SXGN-RC" FP-QPC02SXGN-RC-MFG 2232.28,1323.82 r0 top
J4 "QPC02SXGN-RC" FP-QPC02SXGN-RC-MFG 2232.28,1423.23 r0 top
J5 "2012670005" USB-C_RCP 2034.29,196.02 r0 top locked
J6 "SM2924" SM2924 1082.68,35.83 r90 top
MH1 "PAD0009" MH_300_275_NPTH 137.8,138.66 r0 top
MH2 "PAD0009" MH_300_275_NPTH 2421.26,138.66 r0 top
MH3 "PAD0009" MH_300_275_NPTH 2421.26,2067.8 r0 top
MH4 "PAD0009" MH_300_275_NPTH 137.8,2067.8 r0 top
R1 "RC0603JR-070RL" 0603_res_rnd 1196.85,641.73 r270 top
R2 "RC0603JR-070RL" 0603_res_ab_ra 1174.58,493.48 r225 top
R3 "RC0603JR-070RL" 0603_res_rnd 1165.35,716.54 r0 top
R4 "RC0603JR-070RL" 0603_res_rnd 1165.35,562.01 r0 top
R5 "ERJ-3GEY0R00V" 0603_res 1068.17,1890 r90 top
R6 "ERJ-3GEY0R00V" 0603_res 970,1890 r90 top
R7 "ERJ-3GEY0R00V" 0603_res 1117.9,1889.87 r90 top
R8 "ERJ-3GEY0R00V" 0603_res 1610,1890 r90 top
R9 "ERJ-3GEY0R00V" 0603_res 2105,1890 r90 top
R10 "ERJ-3GEY0R00V" 0603_res 1020,1890 r90 top
R11 "MCR01MZPF4702" 0402_res 1417.32,1190.94 r270 top
R12 "MCR01MZPF4702" 0402_res 1515.75,1190.94 r270 top
R13 "MCR01MZPF4702" 0402_res 1466.54,1190.94 r270 top
R14 "MCR01MZPF4702" 0402_res 1368.11,1190.94 r270 top
R15 "MCR01MZPF4702" 0402_res 1564.96,1190.94 r270 top
R16 "ERJ-3GEY0R00V" 0603_res 1424.43,1889.17 r90 top
R17 "ERJ-3GEY0R00V" 0603_res 1375.34,1889.17 r90 top
R18 "ERJ-3GEY0R00V" 0603_res 1324.43,1889.17 r90 top
R19 "ERJ-3GEY0R00V" 0603_res 1474.43,1889.17 r90 top
R20 "RC0402FR-073K9L" 0402_res 2217.5,1698.08 r0 top
R21 "RC0402FR-073K9L" 0402_res 2177.5,1913.08 r270 top
R22 "RC0402FR-073K9L" 0402_res 2247.5,1913.08 r270 top
R23 "ERJ-3GEY0R00V" 0603_res 1520,1375 r270 bottom
R24 "ERJ-3GEY0R00V" 0603_res 1570,1375 r270 bottom
R25 "ERJ-3GEY0R00V" 0603_res 1320,1375 r270 bottom
R26 "ERJ-3GEY0R00V" 0603_res 1420,1375 r270 bottom
R27 "ERJ-3GEY0R00V" 0603_res 1470,1375 r270 bottom
R28 "ERJ-3GEY0R00V" 0603_res 1370,1375 r270 bottom
R29 "ERJ-3GEY0R00V" 0603_res 1670,1890 r90 top
R30 "ERJ-3GEY0R00V" 0603_res 1845,1890 r90 top
R31 "ERJ-3GEY0R00V" 0603_res 1920,1890 r90 top
R32 "ERJ-3GEY0R00V" 0603_res 830,1885 r90 top
R33 "ERJ-3GEY0R00V" 0603_res 2050,1890 r90 top
R34 "ERJ-3GEY0R00V" 0603_res 770,1885 r90 top
R35 "ERJ-3GEY0R00V" 0603_res 1984.96,1889.7 r90 top
R36 "RC0402FR-07220KL" 0402_res 1210.06,866.34 r270 top
R37 "RG1608P-103-B-T5" 0603_res 535,1880 r90 top
R38 "ERJ-3GEY0R00V" 0603_res 1735,1890 r90 top
R39 "RC0402FR-07330RL" 0402_res 572.83,90.55 r0 top
R40 "RC0402FR-07330RL" 0402_res 682.09,90.55 r180 top
R41 "RC0603JR-070RL" 0603_res_rnd 2395.67,503.94 r180 top
R42 "MCR01MZPF3300" 0402_res 2484.36,1061.26 r270 top
R43 "MCR01MZPF3300" 0402_res 2484.36,1261.93 r270 top
R44 "RC0603JR-070RL" 0603_res_rnd 2309.06,549.21 r90 top
R45 "RC0402FR-075K1L" 0402_res 1741.14,309.06 r270 top
R46 "RC0402FR-075K1L" 0402_res 1787.4,310.04 r90 top
S1 "B3U-1000P" B3U-1000P 255,1835 r270 top
TP1 "TP-BLK" FP-5001-MFG 1800.2,554.13 r0 top
TP2 "TP-BLK" FP-5001-MFG 1781.5,1418.31 r0 top
TP3 "TP-BLK" FP-5001-MFG 156.5,1596.46 r0 top
U1 "MM8108-MF15" MF15 1335,731.26 r90 top
U2 "AT24C32D-STUM-T" SOT-23_5 2212.5,1798.08 r270 top
U3 "TLV75733PDYDR" TLV75533PDYDR 2347.44,743.11 r90 top
U4 "SP3401-02UTG" SP3401-02UTG-Footprint-1 2051.65,394.27 r90 top
VS1 "ESD5Z5.0T1G" SOD-523 2270.67,456.69 r180 top

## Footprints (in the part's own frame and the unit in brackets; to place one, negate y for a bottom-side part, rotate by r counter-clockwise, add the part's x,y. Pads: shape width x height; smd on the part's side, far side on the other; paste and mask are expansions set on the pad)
0402_cap [mil]
  rect 22x20 smd: 1(-17,0) 2(17,0)
0402_cap_rnd [mil]
  rrect50% 22x20 smd mask+0: 1(-17,0) 2(17,0)
0402_res [mil]
  rect 22x20 smd: 1(-17,0) 2(17,0)
0603_cap [mm]
  rect 0.8x0.8 smd: 1(-0.8,0) 2(0.8,0)
0603_res [mm]
  rect 0.8x0.8 smd: 1(-0.8,0) 2(0.8,0)
  silkscreen extent -0.15,-0.33 0.15,0.33
0603_res_ab_ra [mm]
  rrect50% 0.8x0.8 smd: A(-0.8,0) B(0.8,0) C(-0.8,1.6)
0603_res_rnd [mm]
  rrect50% 0.8x0.8 smd: 1(-0.8,0) 2(0.8,0)
  silkscreen extent -0.15,-0.33 0.15,0.33
B3U-1000P [mm]
  rect 0.8x1.7 smd: 1(-1.7,0) 2(1.7,0)
FIDUCIAL_1MM [mm]
  round 1 smd paste-1 mask+0: 1(0,0)
FP-5001-MFG [mm]
  round 1.57 hole 1.016 paste+0 mask+0: 1(0,0)
  silkscreen extent -1.35,-1.34 1.35,1.34
FP-QPC02SXGN-RC-MFG [mil]
FTSH_108_D_K [mil]
  rect 40x40 hole 23.62: 1(-175,-25)
  round 40 hole 23.62: 2(-175,25) 3(-125,-25) 4(-125,25) 5(-75,-25) 6(-75,25) 7(-25,-25) 8(-25,25) 9(25,-25) 10(25,25) 11(75,-25) 12(75,25) 13(125,-25) 14(125,25) 15(175,-25) 16(175,25)
  silkscreen extent -210,-110 210,110
HDR1X2 [mm] "Connector; Header; 2 Position"
  rect 1.5x1.8 hole 0.9: 1(-1.27,0)
  oval 1.5x1.8 hole 0.9: 2(1.27,0)
  silkscreen extent -2.54,-1.27 2.54,1.27
HDR1X2_DNF [mm] "Connector; Header; 2 Position"
  rect 1.5x1.8 hole 0.9: 1(-1.27,0)
  oval 1.5x1.8 hole 0.9: 2(1.27,0)
  silkscreen extent -2.54,-1.27 2.54,1.27
HDR2X6 [mm] "Connector; Header; 6x2 Position"
  rect 1.5x1.8 hole 0.9: 1(-6.35,-1.27)
  oval 1.5x1.8 hole 0.9: 2(-6.35,1.27) 3(-3.81,-1.27) 4(-3.81,1.27) 5(-1.27,-1.27) 6(-1.27,1.27) 7(1.27,-1.27) 8(1.27,1.27) 9(3.81,-1.27) 10(3.81,1.27) 11(6.35,-1.27) 12(6.35,1.27)
  silkscreen extent -7.62,-2.54 7.62,2.54
HDR2X7 [mm] "Connector; Header; 7x2 Position"
  rect 1.5x1.8 hole 0.9: 1(-7.62,-1.27)
  oval 1.5x1.8 hole 0.9: 2(-7.62,1.27) 3(-5.08,-1.27) 4(-5.08,1.27) 5(-2.54,-1.27) 6(-2.54,1.27) 7(0,-1.27) 8(0,1.27) 9(2.54,-1.27) 10(2.54,1.27) 11(5.08,-1.27) 12(5.08,1.27) 13(7.62,-1.27) 14(7.62,1.27)
  silkscreen extent -8.89,-2.54 8.89,2.54
HDR2X20F [mm] "Connector; Header; 20x2 Position Female"
  rect 1.5x1.8 hole 0.9: 1(-24.13,1.27)
  oval 1.5x1.8 hole 0.9: 2(-24.13,-1.27) 3(-21.59,1.27) 4(-21.59,-1.27) 5(-19.05,1.27) 6(-19.05,-1.27) 7(-16.51,1.27) 8(-16.51,-1.27) 9(-13.97,1.27) 10(-13.97,-1.27) 11(-11.43,1.27) 12(-11.43,-1.27) 13(-8.89,1.27) 14(-8.89,-1.27) 15(-6.35,1.27) 16(-6.35,-1.27) 17(-3.81,1.27) 18(-3.81,-1.27) 19(-1.27,1.27) 20(-1.27,-1.27) 21(1.27,1.27) 22(1.27,-1.27) 23(3.81,1.27) 24(3.81,-1.27) 25(6.35,1.27) 26(6.35,-1.27) 27(8.89,1.27) 28(8.89,-1.27) 29(11.43,1.27) 30(11.43,-1.27) 31(13.97,1.27) 32(13.97,-1.27) 33(16.51,1.27) 34(16.51,-1.27) 35(19.05,1.27) 36(19.05,-1.27) 37(21.59,1.27) 38(21.59,-1.27) 39(24.13,1.27) 40(24.13,-1.27)
  silkscreen extent -25.4,-2.54 25.4,2.54
INF-TSLP-2-20_V [mm] "TSLP, 2-Leads, Body 1x0.6mm, Pitch 0.65mm"
  rect 0.6x0.35 smd: 1(0,0.325) 2(0,-0.325)
  silkscreen extent -0.65,0.28 -0.55,0.37
LED_0402_GREEN [mm]
  rect 0.7x0.5 smd mask+0: A(-0.45,0) K(0.45,0)
  silkscreen extent 0.92,-0.38 1.1,0.35
LED_0402_RED [mm]
  rect 0.7x0.5 smd mask+0: A(-0.45,0) K(0.45,0)
  silkscreen extent 0.92,-0.38 1.1,0.35
MF15 [mm]
  rect 0.6x0.6 smd: 1(0,0) 2(1,0) 3(2,0) 4(3,0) 5(4,0) 6(5,0) 7(6,0) 8(7,0) 9(8,0) 10(9,0) 11(10,0) 12(10,-1) 13(10,-2) 14(10,-3) 15(10,-4) 16(10,-5) 17(10,-6) 18(10,-7) 19(10,-8) 20(10,-9) 21(9,-9) 22(8,-9) 23(7,-9) 24(6,-9) 25(5,-9) 26(4,-9) 27(3,-9) 28(2,-9) 29(1,-9) 30(0,-9) 31(0,-8) 32(0,-7) 33(0,-6) 34(0,-5) 35(0,-4) 36(0,-3) 37(0,-2) 38(0,-1)
  silkscreen extent -0.6,-9.6 10.6,1.55
MH_300_275_NPTH [mm] "Non-plated mount hole M2.5 3.00mm diameter"
  round 2.75 hole 2.75 unplated mask+0: 1(0,0)
  Keep-Out Layer circle w0.2: c0,0 r1.65
SM2924 [mil] "Footprint and 3D model for SM2924 component"
  rect 122.83x39.37 smd paste-20: 1(287.01,0)
  rect 192.32x70.08 hole 20 copper offset 11.61,5.39 mask+0: 2(55,170)
  rect 192.32x70.08 hole 20 copper offset 11.61,-5.39 mask+0: 2(55,-170)
  rect 108x97.24 smd paste-20: 2(271.63,-127.5) 2(271.63,127.5)
  Top Layer region: 140.92,226.93 160.92,226.93 160.92,284.54 140.92,284.54
  Top Layer region: 100.88,226.9 120.88,226.9 120.88,284.51 100.88,284.51
  Top Layer region: 60.94,226.92 80.94,226.92 80.94,284.53 60.94,284.53
  Top Layer region: 20.9,226.92 40.9,226.92 40.9,284.53 20.9,284.53
  Top Layer region: -19.05,226.92 0.95,226.92 0.95,284.53 -19.05,284.53
  Top Layer region: 180.88,226.9 200.88,226.9 200.88,284.51 180.88,284.51
  Top Layer region: 220.92,226.9 240.92,226.9 240.92,284.51 220.92,284.51
  Top Layer region: 285.67,94.63 285.67,78.88 343.28,78.88 343.28,94.63
  Top Layer region: 305.61,137.48 325.61,137.48 325.61,195.09 305.61,195.09
  Top Layer region: 343.26,114.65 343.26,134.65 285.65,134.65 285.65,114.65
  Top Layer region: 265.59,137.5 285.59,137.5 285.59,195.11 265.59,195.11
  Top Layer region: 343.22,154.65 343.22,174.65 285.61,174.65 285.61,154.65
  Top Layer region: 285.62,-154.63 285.62,-174.63 343.23,-174.63 343.23,-154.63
  Top Layer region: 265.59,-195.11 285.59,-195.11 285.59,-137.5 265.59,-137.5
  Top Layer region: 285.66,-114.63 285.66,-134.63 343.27,-134.63 343.27,-114.63
  Top Layer region: 305.62,-195.11 325.62,-195.11 325.62,-137.5 305.62,-137.5
  Top Layer region: 227.98,206.09 227.98,186.09 285.59,186.09 285.59,206.09
  Top Layer region: -19.05,-284.52 0.95,-284.52 0.95,-226.92 -19.05,-226.92
  Top Layer region: 20.9,-284.53 40.9,-284.53 40.9,-226.92 20.9,-226.92
  Top Layer region: 60.94,-284.53 80.94,-284.53 80.94,-226.92 60.94,-226.92
  Top Layer region: 100.88,-284.54 120.88,-284.54 120.88,-226.93 100.88,-226.93
  Top Layer region: 140.92,-284.51 160.92,-284.51 160.92,-226.9 140.92,-226.9
  Top Layer region: 220.92,-284.54 240.92,-284.54 240.92,-226.93 220.92,-226.93
  Top Layer region: 180.89,-284.54 200.89,-284.54 200.89,-226.93 180.89,-226.93
  Top Layer region: 285.59,-206.12 285.59,-186.12 227.98,-186.12 227.98,-206.12
  Top Layer region: 227.96,246.11 227.96,226.11 285.57,226.11 285.57,246.11
  Top Layer region: 227.96,-226.11 227.96,-246.11 285.57,-246.11 285.57,-226.11
  Mid Layer 1 region: 343.26,-94.6 343.26,-78.72 285.65,-78.72 285.65,-94.6
  Bottom Layer region: 140.92,-192 140.92,-212 183.45,-212 183.45,-192
  Bottom Layer region: 140.92,-234.52 160.92,-234.52 160.92,-192 140.92,-192
  Bottom Layer region: 100.88,-234.56 120.88,-234.56 120.88,-192.02 100.88,-192.02
  Bottom Layer region: 60.92,-234.53 80.92,-234.53 80.92,-192 60.92,-192
  Bottom Layer region: 20.88,-234.53 40.88,-234.53 40.88,-192 20.88,-192
  Bottom Layer region: -19.07,-234.53 0.93,-234.53 0.93,-192 -19.07,-192
  Bottom Layer region: 183.45,192 183.45,212 140.92,212 140.92,192
  Bottom Layer region: 140.92,192 160.92,192 160.92,234.52 140.92,234.52
  Bottom Layer region: 100.88,191.98 120.88,191.98 120.88,234.51 100.88,234.51
  Bottom Layer region: 60.92,192 80.92,192 80.92,234.53 60.92,234.53
  Bottom Layer region: 20.88,192 40.88,192 40.88,234.53 20.88,234.53
  Bottom Layer region: -19.07,192 0.93,192 0.93,234.53 -19.07,234.53
  Keep-Out Layer lines w0.5: -44.53,140.35 171.26,140.35 cw(c190.94,140.35) 210.63,140.35 210.63,-140.35 cw(c190.94,-140.35) 171.26,-140.35 -44.53,-140.35
  silkscreen extent -293,-197 289,197
SOD-523 [mm]
  rect 0.5x0.4 smd: A(0.65,0) K(-0.65,0)
  silkscreen extent -1.2,-0.38 0.4,0.4
SOIC127P790X216-8N [mm]
  rect 1.65x0.65 smd: 1(-3.6,1.905) 2(-3.6,0.635) 3(-3.6,-0.635) 4(-3.6,-1.905) 5(3.6,-1.905) 6(3.6,-0.635) 7(3.6,0.635) 8(3.6,1.905)
  silkscreen extent -3.56,-2.64 2.42,3.18
SOT-23_5 [mil]
  rect 39x25 smd: 1(-50,37.5) 2(-50,0) 3(-50,-37.5) 4(50,-37.5) 5(50,37.5)
  silkscreen extent -20,-60 20,60
SP3401-02UTG-Footprint-1 [mm]
  rect 0.48x0.3 smd mask+0: 1(-0.314,0.687) 2(-0.314,0.187) 5(0.36,0.187) 6(0.36,0.687)
  rect 0.55x0.4 smd mask+0: 3(-0.292,-0.313)
  rect 0.42x0.4 smd mask+0: 4(0.403,-0.321)
  silkscreen extent -0.49,1.16 -0.29,1.36
TLV75533PDYDR [mm]
  rect 1.1x0.6 smd paste+0 mask+0: 1(-1.3,0.95) 2(-1.3,0) 3(-1.3,-0.95) 4(1.3,-0.95) 5(1.3,0.95)
  rect 1.3x2.9 smd paste-1.437 mask+0: 6(0,0)
  silkscreen extent -1.57,-1.9 0.87,2.05
U_FL-R-SMT [mm]
  rrect50% 1x1 smd: 1(0,-1.5)
  rect 1.05x2.2 smd: 2(-1.475,0) 3(1.475,0)
  Top Layer keep-out region: -1.5,-1.551 1.5,-1.551 1.5,1.549 -1.5,1.549
  silkscreen extent -1.55,-1.52 1.55,1.5
USB-C_RCP [mm] "CONN RCP USB3.1 TYPEC 24P SMD RA"
  rect 0.28x0.7 smd mask+0: A1(-3,3.085) A2(-2.5,3.085) A3(-2,3.085) A4(-1.5,3.085) A5(-1,3.085) A6(-0.5,3.085) A7(0.5,3.085) A8(1,3.085) A9(1.5,3.085) A10(2,3.085) A11(2.5,3.085) A12(3,3.085) B2(2.25,1.385) B3(1.75,1.385) B4(1.25,1.385) B5(0.75,1.385) B6(0.25,1.385) B7(-0.25,1.385) B8(-0.75,1.385) B9(-1.25,1.385) B10(-1.75,1.385) B11(-2.25,1.385)
  rect 0.88x0.7 smd mask+0: B1(3.05,1.385) B12(-3.05,1.385)
  oval 1.1x2.1 hole 0.6 slot 1.6 at 90 deg: SH1(-4.32,2.275) SH2(4.32,2.275)
  oval 1.1x3.6 hole 0.6 slot 2.1 at 90 deg copper offset 0,0.5: SH3(4.62,-3.085) SH4(-4.62,-3.085)
  silkscreen extent -3.76,3.65 -3.51,3.9

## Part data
C1 C3 C5 C7 C8 C9: library part CAP0025-15, "CAP CER 100NF 10V ±10% X7R 0402"
C2 C4 C6 C13: library part CAP0197-10, "CAP CER 10UF 25V ±20% X5R 0603"
C10: library part CAP0027-15, "CAP CER 2.2UF 6.3V ±20% X5R 0402"
C11 C12: library part CAP0046-16, "CAP CER 10UF 10V 20% X5R 0402"
D1 D2: library part DIO0089-8, "ESD103B102 Series 1 Line 15 V 0.2pF Bi-Direction TVS Protection Device-TSLP-2-20"
D3 D5 D6: library part DIO0053-7, "LED GREEN 0402 SMD"
D4: library part DIO0052-9, "LED RED 0402 SMD"
FID1 FID2 FID3: library part FID00000-1
H1: library part JCK0091-7, "U.FL RF Connector"
H3: library part HDR0067-2, "Conn Straight Header 2x1 0.100\" 2 POS (DNF)"
H4: library part HDR0101-2, "Conn Female Header 20x2 0.100\" 40 POS"
H5 H7: library part HDR0110-2, "Board Connector, 16 Contact(s), 2 Row(s), Male, Straight, 0.05 inch Pitch, Solder Terminal, Locking"
H6: library part HDR0095-2, "Conn Straight Header 7x2 0.100\" 14 POS"
H8: library part HDR0006-4, "Conn Straight Header 2x1 0.100\" 2 POS"
H9: library part HDR0014-2, "Conn Straight Header 6x2 0.100\" 12 POS"
IC1: library part ICT0225-3, "Integrated Circuit"
J1 J2 J3 J4: library part CMP-00006-7, "Shunts/Jumper Connector"
J5: library part JCK0027-1, "CONN RCP USB3.1 TYPEC 24P SMD RA"
J6: library part JCK0138-23, "Wanshih RF SMD SMA connector with 2 GND pillars - Smaller Connector Barrel"
MH1 MH2 MH3 MH4: library part PAD0009-2, "MH NPTH 3.00mm DIA 2.75mm HOLE"
R1 R3 R4 R41 R44: library part RES0119-8, "RES SMD 0R OHM ±5% 1/10W 0603"
R2: library part RES0284-2, "RES 0 OHM JUMPER 1/10W 0603"
R5 R6 R7 R8 R9 R10 R16 R17 R18 R19 R23 R24 R25 R26 R27 R28 R29 R30 R31 R32 R33 R34 R35 R38: library part RES0003-8, "RES SMD 0R OHM ±1% 1/10W 0603"
R11 R12 R13 R14 R15: library part RES0086-13, "RES SMD 47K OHM ±1% 1/16W 0402"
R20 R21 R22: library part RES0204-13, "RES SMD 3K9 OHM ±1% 1/16W 0402"
R36: library part RES0064-13, "RES SMD 220K OHM ±1% 1/16W 0402"
R37: library part RES0143-8, "RES SMD 10K OHM ±0.1% 1/10W 0603"
R39 R40: library part RES0025-14, "RES SMD 330R OHM ±1% 1/16W 0402"
R42 R43: library part RES0073-13, "RES SMD 330R OHM ±1% 1/16W 0402"
R45 R46: library part RES0027-13, "RES SMD 5K1 OHM ±1% 1/16W 0402"
S1: library part SWH0022-1, "SWITCH TACTILE SPST-NO 0.05A 12V"
TP1 TP2 TP3: library part TPN0006-3, "Test Point PCB, Black 0.040\"D"
U1: library part MOD0024-12
U2: library part ICT0037-3, "IC EEPROM 32KBIT I2C SOT23-5"
U3: library part ICT0296-2, "1-A, low-IQ high-accuracy low-dropout (LDO) voltage regulator with enable 5-SOT-23 -40 to 125"
U4: library part CMP-00020-9, "9V Clamp 10A (8/20µs) Ipp Tvs Diode Surface Mount 6-µDFN (1.6x1)"
VS1: library part DIO0073-2, "TVS Diode,5V@9.4Amp, SOD-523 SMD"

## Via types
v1: diameter 19.68, hole 9.84, Top Layer to Bottom Layer, tented both sides, 584 vias
v2: diameter 23.62, hole 11.81, Top Layer to Bottom Layer, tented both sides, 25 vias
v3: diameter 40, hole 20, Top Layer to Bottom Layer, 12 vias

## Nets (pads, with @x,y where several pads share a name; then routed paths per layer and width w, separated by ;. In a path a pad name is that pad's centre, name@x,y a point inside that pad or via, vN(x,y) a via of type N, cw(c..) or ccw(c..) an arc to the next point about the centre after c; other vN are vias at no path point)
5V_USB: C13.1 J5.A4 J5.A9 J5.B4 J5.B9 R41.2 R44.1 VS1.K | length 1094.7
  Top Layer w10: v1(1960,287.86) 1961.85,289.71 1965.88,289.71 1974.72,298.56 1974.72,316.97 J5.A4@1975.24,317.48 ; v1(1970.47,220.93) 1972.33,222.78 1975.72,222.78 1984.57,231.63 1984.57,237.82 1984.57,263.28 1984.57,279.57 v1(1985,280) ; v1(2077.87,285) 2077.87,282.38 2082.99,277.26 2082.99,251.06 J5.B4@2083.5,250.55 2084.02,250.04 2084.02,228.64 2088.58,224.08 v1(2088.58,221.46) ; v1(2082.68,347.44) 2082.68,346.9 2092.83,336.74 2092.83,317.99 2093.86,316.97 2093.86,300.65 2102.48,292.03 2102.48,289.25 v1(2104.33,287.4)
  Top Layer w50: v1(2219.49,403.54) v1(2261.81,403.54) 2309.06,403.54 C13.1@2310.04,402.56 ; 2289.37,411.42 2303.51,425.56 ; 2309.06,469.49 R44.1@2309.06,517.72 2313.98,512.8 R41.2@2355.32,512.8 ; C13.1@2310.04,413.39 2310.04,451.77
  Mid Layer 1 w50: v1(1970.47,220.93) 1970.47,352.36 2023.62,405.51 2106.45,405.51 2109.4,402.56 2112.3,402.56 2113.29,403.54 v1(2219.49,403.54) v1(2261.81,403.54) ; v1@2091.53,226.38 2091.53,347.44 2091.53,351.75 ; v1@2091.9,347.44 2091.9,382.16
CC1: J5.A5 R45.1 | length 379.6
  Top Layer w10: R45.1@1742.13,320.87 1742.13,377.95 1753.94,389.76 1812.99,389.76 1838.58,415.35 1867.13,415.35 1897.64,384.84 1949.8,384.84 1994.41,340.24 1994.41,317.6 J5.A5@1995.08,316.93
CC2: J5.B5 R46.1 | length 378.7
  Top Layer w11.02: R46.1@1786.42,292.32 1789.66,289.08 1789.66,259.55 1867.13,182.09 2026.57,182.09 2063.82,219.33 J5.B5@2063.82,242.28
